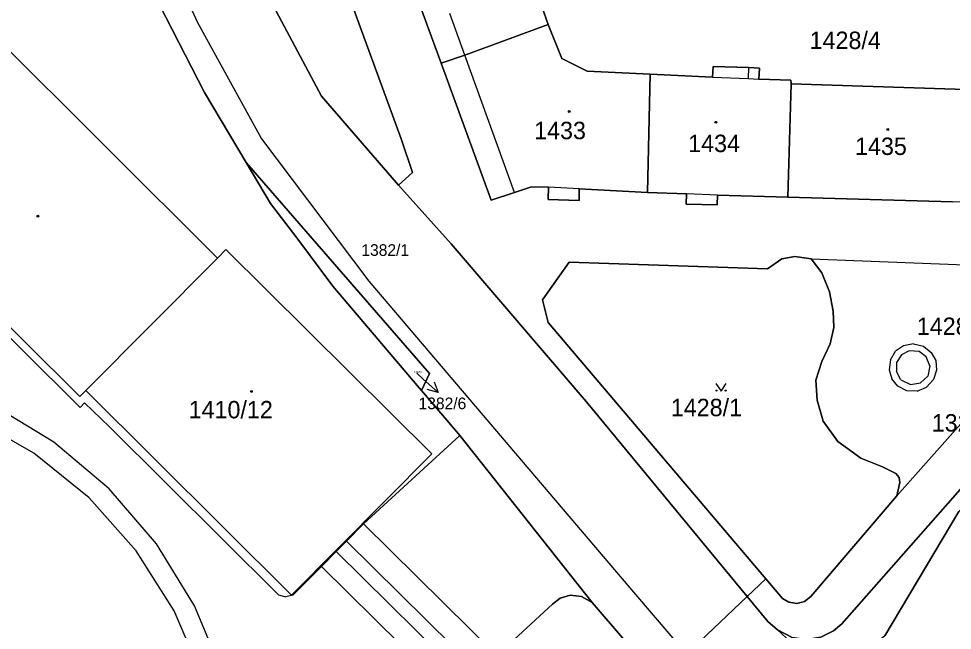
# Model space of a CAD drawing. Extents: x -598934 to -598196, y -1162208 to -1161502.
# Drawn here: x -598686.2 to -598595, y -1161757.9 to -1161698.2 of the extents above; entities that cross this region are included whole.
import ezdxf

# ---------------------------------------------------------------- set-up
doc = ezdxf.new("R2010")
doc.units = 0
for name, color, linetype in [('KN_CAR_KR', 7, 'Continuous'), ('KN_KULTURY', 7, 'Continuous'), ('KN_PARC_CIS_POM', 7, 'Continuous'), ('KN_PARC_CIS_POZ', 7, 'Continuous'), ('KN_PARC_CIS_STAV', 7, 'Continuous'), ('KN_PARC_PLOCHA', 7, 'Continuous'), ('PARC_C_SIPKA', 7, 'Continuous'), ('parcely_l', 7, 'Continuous')]:
    doc.layers.add(name, color=color, linetype=linetype)

msp = doc.modelspace()

# ---------------------------------------------------------------- linework, layer by layer
at = {"layer": 'KN_CAR_KR'}
for points in [[(-598671.58, -1161692.3), (-598668.78, -1161698.56)], [(-598668.78, -1161698.56), (-598662.49, -1161709.96)], [(-598642.64, -1161701.79), (-598644.1, -1161697.73)], [(-598680.22, -1161735.12), (-598702.18, -1161713.33), (-598688.73, -1161699.76)], [(-598688.73, -1161699.76), (-598666.78, -1161721.61)], [(-598637.79, -1161715.19), (-598642.64, -1161701.79)], [(-598614.95, -1161702.99), (-598614.99, -1161704.07)], [(-598618.47, -1161703.94), (-598614.99, -1161704.07)], [(-598614.99, -1161704.07), (-598613.95, -1161704.13)], [(-598662.49, -1161709.96), (-598652.02, -1161723.86)], [(-598703.13, -1161713.4), (-598680.2, -1161736.17)], [(-598631.47, -1161714.85), (-598634.48, -1161714.67)], [(-598617.98, -1161715.47), (-598620.99, -1161715.34)], [(-598608.83, -1161721.67), (-598586.27, -1161722.54)], [(-598652.02, -1161723.86), (-598625.96, -1161754.43)], [(-598599.81, -1161730.15), (-598600.59, -1161730.68)], [(-598598.82, -1161729.96), (-598599.81, -1161730.15)], [(-598598.82, -1161729.96), (-598597.86, -1161730.21)], [(-598597.86, -1161730.21), (-598597.12, -1161730.8)], [(-598601.09, -1161731.54), (-598600.59, -1161730.68)], [(-598600.02, -1161731.05), (-598600.5, -1161731.8)], [(-598599.25, -1161730.65), (-598600.02, -1161731.05)], [(-598598.29, -1161730.72), (-598599.25, -1161730.65)], [(-598597.59, -1161731.23), (-598598.29, -1161730.72)], [(-598597.24, -1161732.12), (-598597.59, -1161731.23)], [(-598597.12, -1161730.8), (-598596.66, -1161731.61)], [(-598601.09, -1161731.54), (-598601.2, -1161732.51)], [(-598600.5, -1161731.8), (-598600.51, -1161732.68)], [(-598597.24, -1161732.12), (-598597.45, -1161733.11)], [(-598596.66, -1161731.61), (-598596.58, -1161732.53)], [(-598601.2, -1161732.51), (-598600.96, -1161733.37)], [(-598600.07, -1161733.47), (-598600.51, -1161732.68)], [(-598598.15, -1161733.78), (-598597.45, -1161733.11)], [(-598596.58, -1161732.53), (-598596.88, -1161733.45)], [(-598600.38, -1161734.1), (-598600.96, -1161733.37)], [(-598599.49, -1161734.54), (-598600.38, -1161734.1)], [(-598600.07, -1161733.47), (-598599.14, -1161733.94)], [(-598599.14, -1161733.94), (-598598.15, -1161733.78)], [(-598597.57, -1161734.21), (-598596.88, -1161733.45)], [(-598680.22, -1161735.12), (-598679.63, -1161734.52)], [(-598598.47, -1161734.58), (-598599.49, -1161734.54)], [(-598598.47, -1161734.58), (-598597.57, -1161734.21)], [(-598682.76, -1161739.56), (-598688.83, -1161735.9)], [(-598680.2, -1161736.17), (-598679.76, -1161735.73)], [(-598679.76, -1161735.73), (-598677.31, -1161738.08)], [(-598684.7, -1161740.65), (-598690.71, -1161737.21)], [(-598660.81, -1161754.45), (-598677.31, -1161738.08)], [(-598677.35, -1161744.13), (-598682.76, -1161739.56)], [(-598652.52, -1161747.55), (-598643.12, -1161738.93)], [(-598679.32, -1161745.01), (-598684.7, -1161740.65)], [(-598672.73, -1161749.5), (-598677.35, -1161744.13)], [(-598674.72, -1161750.18), (-598679.32, -1161745.01)], [(-598654.19, -1161749.24), (-598652.52, -1161747.55)], [(-598652.52, -1161747.55), (-598639.5, -1161760.37)], [(-598669.01, -1161755.52), (-598672.73, -1161749.5)], [(-598655.18, -1161750.24), (-598654.19, -1161749.24)], [(-598654.19, -1161749.24), (-598641.2, -1161762.05)], [(-598671, -1161756.02), (-598674.72, -1161750.18)], [(-598656.63, -1161751.69), (-598655.18, -1161750.24)], [(-598642.2, -1161763.04), (-598655.18, -1161750.24)], [(-598659.43, -1161754.51), (-598656.63, -1161751.69)], [(-598656.63, -1161751.69), (-598643.67, -1161764.49)], [(-598660.81, -1161754.45), (-598660.11, -1161754.66)], [(-598659.43, -1161754.51), (-598660.11, -1161754.66)], [(-598625.96, -1161754.43), (-598621.01, -1161760.25)], [(-598668.28, -1161762.39), (-598671, -1161756.02)], [(-598666.28, -1161762.06), (-598669.01, -1161755.52)]]:
    msp.add_lwpolyline(points, dxfattribs=at)
at = {"layer": 'KN_KULTURY'}
msp.add_lwpolyline([(-598618.122, -1161733.832), (-598617.622, -1161734.582), (-598617.122, -1161733.832)], dxfattribs=at)
for centre, radius in [((-598632.44, -1161707.3), 0.09), ((-598632.44, -1161707.3), 0.0398), ((-598618.13, -1161708.35), 0.09), ((-598618.13, -1161708.35), 0.0398), ((-598601.35, -1161709.06), 0.09), ((-598601.35, -1161709.06), 0.0398), ((-598684.31, -1161717.51), 0.09), ((-598684.31, -1161717.51), 0.0398), ((-598663.47, -1161734.61), 0.09), ((-598663.47, -1161734.61), 0.0398), ((-598618.072, -1161734.531), 0.05), ((-598617.173, -1161734.531), 0.05)]:
    msp.add_circle(centre, radius, dxfattribs=at)
at = {"layer": 'KN_PARC_PLOCHA'}
for points in [[(-598601.64, -1161758.47), (-598594.41, -1161746.34), (-598574.71, -1161725.04), (-598562.49, -1161716.2), (-598546.26, -1161698.46), (-598538.27, -1161689.71), (-598508.71, -1161657.4), (-598500.6, -1161648.49), (-598493.91, -1161641.2), (-598488.42, -1161635.24), (-598481.9, -1161628.09), (-598472.12, -1161617.39), (-598454.81, -1161598.51), (-598446.33, -1161589.22), (-598435.01, -1161576.84), (-598438.32, -1161581.74), (-598452.8, -1161599.01), (-598453, -1161599.23), (-598502.88, -1161660.58), (-598537.16, -1161698.1), (-598569.06, -1161732.86), (-598601.28, -1161767.71)], [(-598686.46, -1161632.58), (-598684.05, -1161640.04), (-598681.2, -1161648.82), (-598672.1, -1161675.27), (-598670.33, -1161680.01), (-598668.86, -1161682.84), (-598656.62, -1161705.79), (-598649.12, -1161714.49), (-598643.96, -1161720.2), (-598630.79, -1161735.6), (-598615.08, -1161754.64), (-598621.01, -1161760.25)], [(-598623.69, -1161762.79), (-598630.21, -1161755.2), (-598643.12, -1161738.93), (-598643.44, -1161738.54), (-598646.87, -1161734.51), (-598646.1, -1161732.88), (-598663.98, -1161712.27), (-598668.05, -1161705.44), (-598673.72, -1161694.38), (-598671.58, -1161692.3), (-598675.38, -1161685.5), (-598678.03, -1161679.94), (-598687.48, -1161651.51)], [(-598587.23, -1161729.92), (-598600.45, -1161744.8), (-598600.16, -1161743.51), (-598600.25, -1161743.01), (-598600.57, -1161742.61), (-598601.85, -1161741.97), (-598603.98, -1161741.13), (-598606.23, -1161739.5), (-598607.65, -1161737.5), (-598608.25, -1161735.47), (-598608.37, -1161733.5), (-598607.8, -1161731.7), (-598606.98, -1161729.97), (-598606.62, -1161728.36), (-598606.67, -1161726.78), (-598607.04, -1161724.88), (-598607.77, -1161723.05), (-598608.83, -1161721.67), (-598610.42, -1161721.45), (-598611.7, -1161721.66), (-598613.1, -1161722.64), (-598632.45, -1161722), (-598635.04, -1161725.66), (-598634.5, -1161727.89), (-598613.25, -1161752.9), (-598615.08, -1161754.64), (-598630.79, -1161735.6), (-598643.96, -1161720.2), (-598649.12, -1161714.49), (-598647.75, -1161713.25), (-598648.85, -1161709.97), (-598659.88, -1161679.81)], [(-598650.79, -1161686.62), (-598644.94, -1161702.57), (-598640.08, -1161715.96), (-598637.79, -1161715.19), (-598636.14, -1161714.64), (-598634.48, -1161714.67), (-598634.5, -1161715.87), (-598631.48, -1161715.97), (-598631.47, -1161714.85), (-598624.8, -1161715.21), (-598620.99, -1161715.34), (-598621.04, -1161716.35), (-598618.01, -1161716.4), (-598617.98, -1161715.47), (-598611.1, -1161715.67), (-598595.03, -1161716.12)], [(-598703.13, -1161713.4), (-598684.2, -1161694.1), (-598678.92, -1161689.98), (-598673.96, -1161694.59), (-598673.72, -1161694.38), (-598668.05, -1161705.44), (-598663.98, -1161712.27), (-598661.59, -1161716.28), (-598659.05, -1161719.64), (-598655.51, -1161724.33), (-598649.66, -1161731.23), (-598647.28, -1161734.03), (-598646.87, -1161734.51), (-598643.44, -1161738.54), (-598643.12, -1161738.93), (-598630.21, -1161755.2), (-598631.23, -1161754.62), (-598632.35, -1161754.49), (-598633.32, -1161754.79), (-598634.09, -1161755.38), (-598639.5, -1161760.37)], [(-598591.78, -1161705.2), (-598610.79, -1161704.61), (-598610.81, -1161704.23), (-598613.95, -1161704.13), (-598613.87, -1161703.06), (-598614.95, -1161702.99), (-598618.4, -1161702.91), (-598618.47, -1161703.94), (-598624.53, -1161703.67), (-598630.7, -1161703.37), (-598633.17, -1161702.14), (-598634.49, -1161698.82), (-598635.53, -1161695.8)], [(-598575.72, -1161723.15), (-598605.82, -1161757.29), (-598606.66, -1161757.99)], [(-598610.67, -1161758.61), (-598612.11, -1161757.87), (-598613.07, -1161757.07), (-598615.08, -1161754.64), (-598613.25, -1161752.9), (-598611.61, -1161754.82), (-598611, -1161755.19), (-598610.24, -1161755.32), (-598609.49, -1161755.12), (-598608.87, -1161754.64), (-598600.45, -1161744.8), (-598587.23, -1161729.92)], [(-598639.5, -1161760.37), (-598634.09, -1161755.38), (-598633.32, -1161754.79), (-598632.35, -1161754.49), (-598631.23, -1161754.62), (-598630.21, -1161755.2), (-598623.69, -1161762.79)], [(-598621.01, -1161760.25), (-598615.08, -1161754.64), (-598613.07, -1161757.07), (-598612.11, -1161757.87), (-598610.85, -1161759.04)]]:
    msp.add_lwpolyline(points, dxfattribs=at)
for points in [[(-598649.12, -1161714.49), (-598656.62, -1161705.79), (-598668.86, -1161682.84), (-598668.89, -1161682.28), (-598668.76, -1161681.75), (-598668.52, -1161681.36), (-598668.17, -1161681.04), (-598661.92, -1161678.6), (-598661.28, -1161678.5), (-598660.64, -1161678.65), (-598660.16, -1161679.12), (-598659.88, -1161679.81), (-598648.85, -1161709.97), (-598647.75, -1161713.25)], [(-598634.49, -1161698.82), (-598642.64, -1161701.79), (-598644.94, -1161702.57), (-598650.79, -1161686.62), (-598648.42, -1161685.75), (-598640.3, -1161682.8), (-598636.95, -1161691.89), (-598635.8, -1161691.46), (-598634.61, -1161694.6), (-598634.32, -1161695.37), (-598635.53, -1161695.8)], [(-598624.53, -1161703.67), (-598624.8, -1161715.21), (-598631.47, -1161714.85), (-598631.48, -1161715.97), (-598634.5, -1161715.87), (-598634.48, -1161714.67), (-598636.14, -1161714.64), (-598637.79, -1161715.19), (-598640.08, -1161715.96), (-598644.94, -1161702.57), (-598642.64, -1161701.79), (-598634.49, -1161698.82), (-598633.17, -1161702.14), (-598630.7, -1161703.37)], [(-598610.79, -1161704.61), (-598611.1, -1161715.67), (-598617.98, -1161715.47), (-598618.01, -1161716.4), (-598621.04, -1161716.35), (-598620.99, -1161715.34), (-598624.8, -1161715.21), (-598624.53, -1161703.67), (-598618.47, -1161703.94), (-598618.4, -1161702.91), (-598614.95, -1161702.99), (-598613.87, -1161703.06), (-598613.95, -1161704.13), (-598610.81, -1161704.23)], [(-598591.78, -1161705.2), (-598592.07, -1161716.23), (-598595.03, -1161716.12), (-598611.1, -1161715.67), (-598610.79, -1161704.61)], [(-598646.87, -1161734.51), (-598647.28, -1161734.03), (-598649.66, -1161731.23), (-598655.51, -1161724.33), (-598659.05, -1161719.64), (-598661.59, -1161716.28), (-598663.98, -1161712.27), (-598646.1, -1161732.88)], [(-598645.86, -1161740.69), (-598665.98, -1161720.78), (-598666.78, -1161721.61), (-598679.63, -1161734.52), (-598659.56, -1161754.5)], [(-598645.86, -1161740.69), (-598659.56, -1161754.5), (-598679.63, -1161734.52), (-598666.78, -1161721.61), (-598665.98, -1161720.78)], [(-598600.45, -1161744.8), (-598608.87, -1161754.64), (-598609.49, -1161755.12), (-598610.24, -1161755.32), (-598611, -1161755.19), (-598611.61, -1161754.82), (-598613.25, -1161752.9), (-598634.5, -1161727.89), (-598635.04, -1161725.66), (-598632.45, -1161722), (-598613.1, -1161722.64), (-598611.7, -1161721.66), (-598610.42, -1161721.45), (-598608.83, -1161721.67), (-598607.77, -1161723.05), (-598607.04, -1161724.88), (-598606.67, -1161726.78), (-598606.62, -1161728.36), (-598606.98, -1161729.97), (-598607.8, -1161731.7), (-598608.37, -1161733.5), (-598608.25, -1161735.47), (-598607.65, -1161737.5), (-598606.23, -1161739.5), (-598603.98, -1161741.13), (-598601.85, -1161741.97), (-598600.57, -1161742.61), (-598600.25, -1161743.01), (-598600.16, -1161743.51)], [(-598574.71, -1161725.04), (-598594.41, -1161746.34), (-598601.64, -1161758.47), (-598603.13, -1161759.68), (-598605.13, -1161760.41), (-598607.14, -1161760.52), (-598609.11, -1161760.08), (-598610.85, -1161759.04), (-598612.11, -1161757.87), (-598610.67, -1161758.61), (-598609.3, -1161758.82), (-598607.88, -1161758.59), (-598606.66, -1161757.99), (-598605.82, -1161757.29), (-598575.72, -1161723.15), (-598575.69, -1161723.85)]]:
    msp.add_lwpolyline(points, close=True, dxfattribs=at)
at = {"layer": 'PARC_C_SIPKA'}
for points in [[(-598647.33, -1161732.83), (-598646.73, -1161733.37), (-598645.237, -1161734.716)], [(-598645.645, -1161733.675), (-598645.237, -1161734.716), (-598646.314, -1161734.418)]]:
    msp.add_lwpolyline(points, dxfattribs=at)
at = {"layer": 'parcely_l'}
for points in [[(-598668.86, -1161682.84), (-598668.89, -1161682.28), (-598668.76, -1161681.75), (-598668.52, -1161681.36), (-598668.17, -1161681.04), (-598661.92, -1161678.6), (-598661.28, -1161678.5), (-598660.64, -1161678.65), (-598660.16, -1161679.12), (-598659.88, -1161679.81), (-598648.85, -1161709.97), (-598647.75, -1161713.25), (-598649.12, -1161714.49)], [(-598649.12, -1161714.49), (-598656.62, -1161705.79), (-598668.86, -1161682.84)], [(-598640.3, -1161682.8), (-598636.95, -1161691.89), (-598635.8, -1161691.46), (-598634.61, -1161694.6), (-598634.32, -1161695.37), (-598635.53, -1161695.8), (-598634.49, -1161698.82)], [(-598644.94, -1161702.57), (-598650.79, -1161686.62)], [(-598663.98, -1161712.27), (-598668.05, -1161705.44), (-598673.72, -1161694.38)], [(-598644.94, -1161702.57), (-598642.64, -1161701.79), (-598634.49, -1161698.82)], [(-598634.49, -1161698.82), (-598633.17, -1161702.14), (-598630.7, -1161703.37), (-598624.53, -1161703.67)], [(-598624.8, -1161715.21), (-598631.47, -1161714.85), (-598631.48, -1161715.97), (-598634.5, -1161715.87), (-598634.48, -1161714.67), (-598636.14, -1161714.64), (-598637.79, -1161715.19), (-598640.08, -1161715.96), (-598644.94, -1161702.57)], [(-598624.53, -1161703.67), (-598618.47, -1161703.94), (-598618.4, -1161702.91), (-598614.95, -1161702.99), (-598613.87, -1161703.06), (-598613.95, -1161704.13), (-598610.81, -1161704.23), (-598610.79, -1161704.61)], [(-598624.53, -1161703.67), (-598624.8, -1161715.21)], [(-598610.79, -1161704.61), (-598611.1, -1161715.67)], [(-598610.79, -1161704.61), (-598591.78, -1161705.2)], [(-598646.87, -1161734.51), (-598647.28, -1161734.03), (-598649.66, -1161731.23), (-598655.51, -1161724.33), (-598659.05, -1161719.64), (-598661.59, -1161716.28), (-598663.98, -1161712.27)], [(-598663.98, -1161712.27), (-598646.1, -1161732.88), (-598646.87, -1161734.51)], [(-598649.12, -1161714.49), (-598643.96, -1161720.2), (-598630.79, -1161735.6), (-598615.08, -1161754.64)], [(-598611.1, -1161715.67), (-598617.98, -1161715.47), (-598618.01, -1161716.4), (-598621.04, -1161716.35), (-598620.99, -1161715.34), (-598624.8, -1161715.21)], [(-598592.07, -1161716.23), (-598595.03, -1161716.12), (-598611.1, -1161715.67)], [(-598600.45, -1161744.8), (-598587.23, -1161729.92), (-598586.27, -1161722.54), (-598585.47, -1161716.45)], [(-598645.86, -1161740.69), (-598659.56, -1161754.5), (-598679.63, -1161734.52), (-598666.78, -1161721.61), (-598665.98, -1161720.78), (-598645.86, -1161740.69)], [(-598600.45, -1161744.8), (-598600.16, -1161743.51), (-598600.25, -1161743.01), (-598600.57, -1161742.61), (-598601.85, -1161741.97), (-598603.98, -1161741.13), (-598606.23, -1161739.5), (-598607.65, -1161737.5), (-598608.25, -1161735.47), (-598608.37, -1161733.5), (-598607.8, -1161731.7), (-598606.98, -1161729.97), (-598606.62, -1161728.36), (-598606.67, -1161726.78), (-598607.04, -1161724.88), (-598607.77, -1161723.05), (-598608.83, -1161721.67), (-598610.42, -1161721.45), (-598611.7, -1161721.66), (-598613.1, -1161722.64), (-598632.45, -1161722), (-598635.04, -1161725.66), (-598634.5, -1161727.89), (-598613.25, -1161752.9)], [(-598575.72, -1161723.15), (-598605.82, -1161757.29), (-598606.66, -1161757.99), (-598607.88, -1161758.59), (-598609.3, -1161758.82), (-598610.67, -1161758.61), (-598612.11, -1161757.87)], [(-598574.71, -1161725.04), (-598594.41, -1161746.34), (-598601.64, -1161758.47), (-598603.13, -1161759.68), (-598605.13, -1161760.41), (-598607.14, -1161760.52), (-598609.11, -1161760.08), (-598610.85, -1161759.04), (-598612.11, -1161757.87)], [(-598630.21, -1161755.2), (-598643.12, -1161738.93), (-598643.44, -1161738.54), (-598646.87, -1161734.51)], [(-598613.25, -1161752.9), (-598611.61, -1161754.82), (-598611, -1161755.19), (-598610.24, -1161755.32), (-598609.49, -1161755.12), (-598608.87, -1161754.64), (-598600.45, -1161744.8)], [(-598615.08, -1161754.64), (-598613.25, -1161752.9)], [(-598630.21, -1161755.2), (-598631.23, -1161754.62), (-598632.35, -1161754.49), (-598633.32, -1161754.79), (-598634.09, -1161755.38), (-598639.5, -1161760.37), (-598641.2, -1161762.05), (-598642.2, -1161763.04), (-598643.67, -1161764.49), (-598644.77, -1161765.65), (-598643.54, -1161787.41), (-598647.85, -1161791.6), (-598669.05, -1161813.01), (-598666.97, -1161814.97), (-598665.55, -1161816.3), (-598667.34, -1161818.31), (-598667.91, -1161818.89), (-598669.28, -1161820.59), (-598671.84, -1161818.18)], [(-598615.08, -1161754.64), (-598621.01, -1161760.25)], [(-598612.11, -1161757.87), (-598613.07, -1161757.07), (-598615.08, -1161754.64)], [(-598623.69, -1161762.79), (-598630.21, -1161755.2)]]:
    msp.add_lwpolyline(points, dxfattribs=at)

# ---------------------------------------------------------------- texts
at = {"layer": 'KN_PARC_CIS_POM'}
msp.add_text('1382/6', height=0.2, dxfattribs=at).set_placement((-598647.597, -1161732.83))
at = {"layer": 'KN_PARC_CIS_POZ'}
for s, height, p in [('1428/4', 1.7, (-598608.977, -1161701.2)), ('1382/1', 1.14, (-598652.74, -1161721.388)), ('1428/4', 1.7, (-598598.512, -1161729.1)), ('1382/6', 1.14, (-598647.155, -1161736.352)), ('1428/1', 1.7, (-598622.527, -1161737.03)), ('1327/32', 1.7, (-598597.057, -1161738.53))]:
    msp.add_text(s, height=height, dxfattribs=at).set_placement(p)
at = {"layer": 'KN_PARC_CIS_STAV'}
for s, p in [('1433', (-598635.872, -1161710)), ('1434', (-598620.832, -1161711.26)), ('1435', (-598604.542, -1161711.54)), ('1410/12', (-598669.597, -1161737.24))]:
    msp.add_text(s, height=1.7, dxfattribs=at).set_placement(p)

doc.saveas('drawing.dxf')
